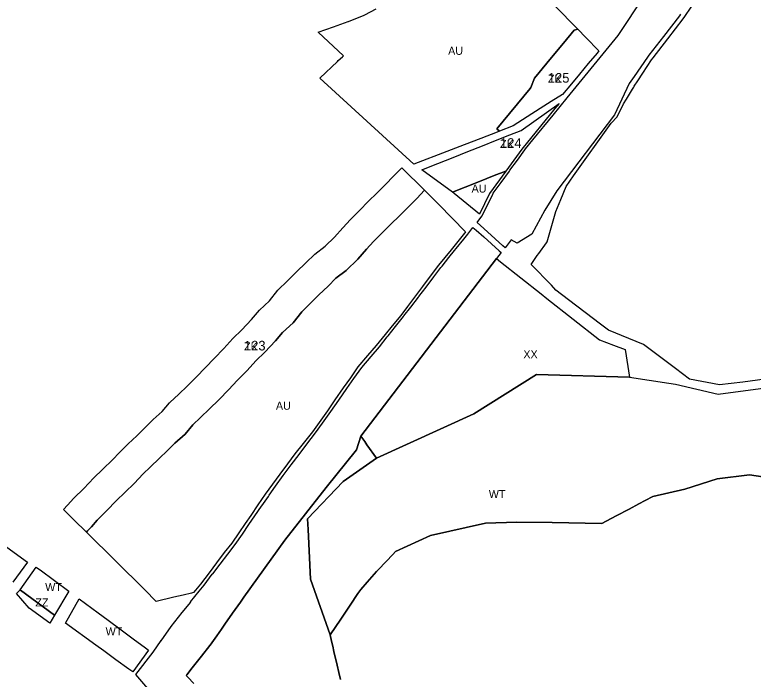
# Model space of a CAD drawing. Extents: x -537068 to -534056, y -1176840 to -1172401.
# Drawn here: x -535533.6 to -535072.7, y -1175950.8 to -1175536.1 of the extents above; entities that cross this region are included whole.
import ezdxf

# ---------------------------------------------------------------- set-up
doc = ezdxf.new("R2010")
doc.units = 0
for name, color, linetype in [('90550013', 7, 'Continuous'), ('90640013', 7, 'Continuous'), ('90670013', 7, 'Continuous'), ('90710023', 7, 'Continuous'), ('90730013', 7, 'Continuous'), ('90750013', 7, 'Continuous'), ('ID_navrh', 7, 'Continuous')]:
    doc.layers.add(name, color=color, linetype=linetype)

msp = doc.modelspace()

# ---------------------------------------------------------------- linework, layer by layer
at = {"layer": '90550013'}
for points in [[(-535050.13, -1175761.47), (-535079.13, -1175765.46), (-535093.81, -1175767.01), (-535112.39, -1175763.44), (-535121.28, -1175756.78), (-535141.07, -1175741.96), (-535150.4, -1175738.16), (-535162.92, -1175733.05), (-535167.89, -1175729.26), (-535192.29, -1175710.66), (-535195.8, -1175707.99), (-535198.63, -1175704.88), (-535211.34, -1175691.91), (-535207.51, -1175686.45), (-535206.57, -1175685.11), (-535201.68, -1175678.47), (-535201.26, -1175677.9), (-535198.75, -1175669.05), (-535195.86, -1175658.84), (-535192.81, -1175651.42), (-535189.46, -1175643.28), (-535184.81, -1175636.58), (-535161.24, -1175603.76), (-535157.66, -1175599.74), (-535153.68, -1175591.72), (-535151.68, -1175588.84), (-535148.03, -1175582.59), (-535147.25, -1175581.25), (-535146.96, -1175580.76), (-535144.78, -1175577.4), (-535141.58, -1175572.48), (-535136.2, -1175564.2), (-535135.2, -1175562.92), (-535125.97, -1175551.1), (-535116.29, -1175538.7), (-535115.3, -1175537.22), (-535107.39, -1175525.43)], [(-535330.29, -1175951), (-535331.33, -1175946.51), (-535332.39, -1175941.92), (-535334.35, -1175933.46), (-535335.09, -1175930.24), (-535335.82, -1175927.11), (-535336.74, -1175923.15), (-535330.15, -1175913.36), (-535324.19, -1175904.5), (-535319.39, -1175897.37), (-535317.62, -1175894.74), (-535313.65, -1175890.19), (-535307.82, -1175883.5), (-535306.83, -1175882.48), (-535301.85, -1175877.35), (-535297.59, -1175872.96), (-535295.86, -1175871.17), (-535274.11, -1175861.12), (-535239.83, -1175853.35), (-535220.25, -1175852.67), (-535198.16, -1175853.04), (-535167.13, -1175853.57), (-535158.18, -1175848.85), (-535150.05, -1175844.57), (-535144.02, -1175841.39), (-535140.05, -1175839.3), (-535135.41, -1175836.85), (-535115.29, -1175832.21), (-535095.1, -1175825.79), (-535075.08, -1175823.28), (-535062.41, -1175825.11)]]:
    msp.add_lwpolyline(points, dxfattribs=at)
msp.add_lwpolyline([(-535307.84, -1175812.81), (-535313.77, -1175804.46), (-535315.14, -1175802.53), (-535317.61, -1175799.04), (-535232.96, -1175688.21), (-535230.41, -1175690.23), (-535204.96, -1175710.36), (-535201.51, -1175713.09), (-535168.68, -1175739.06), (-535159.9, -1175742.34), (-535152.61, -1175745.06), (-535149.83, -1175762.25), (-535207.84, -1175760.65), (-535247.13, -1175785.26)], close=True, dxfattribs=at)
at = {"layer": '90640013'}
for points in [[(-535117.97, -1175535.84), (-535118.65, -1175536.85), (-535128.68, -1175549.71), (-535137.73, -1175561.3), (-535138.67, -1175562.51), (-535146.93, -1175574.59), (-535150.01, -1175579.1), (-535159.16, -1175598.64), (-535195.2, -1175645.89), (-535202.74, -1175658.11), (-535210.95, -1175673.05), (-535220.03, -1175678.6), (-535223.72, -1175676.61), (-535227.6, -1175681.48), (-535228.86, -1175680.34), (-535238.5, -1175671.68), (-535242.98, -1175667.66), (-535245.05, -1175665.69), (-535242.02, -1175661.86), (-535239.38, -1175656.52), (-535235.18, -1175647.99), (-535234.95, -1175647.52), (-535229.99, -1175640.7), (-535224.85, -1175633.62), (-535224.53, -1175633.18), (-535219.88, -1175626.78), (-535215.3, -1175620.47), (-535214.81, -1175619.86), (-535210.21, -1175614.22), (-535197.55, -1175598.71), (-535188.81, -1175587.99), (-535157.02, -1175548.97), (-535140.56, -1175524.19)], [(-535440.26, -1175968.33), (-535457.98, -1175947.84), (-535447.21, -1175933.95), (-535442.17, -1175926.57), (-535442.12, -1175926.9), (-535435.91, -1175917.94), (-535429.03, -1175909.14), (-535423.68, -1175902.65), (-535423.74, -1175902.66), (-535423.87, -1175902.55), (-535418.41, -1175895.85), (-535416.43, -1175893.34), (-535415.4, -1175891.99), (-535410.29, -1175885.31), (-535410.04, -1175884.99), (-535405.39, -1175878.91), (-535400.66, -1175872.73), (-535395.99, -1175866.64), (-535391.55, -1175860.18), (-535387.49, -1175854.29), (-535383.68, -1175848.73), (-535379.57, -1175842.76), (-535379.37, -1175842.48), (-535375.28, -1175836.68), (-535374.77, -1175835.95), (-535370.76, -1175830.27), (-535366.06, -1175823.6), (-535360.98, -1175816.94), (-535356.16, -1175810.6), (-535351.21, -1175804.11), (-535345.85, -1175797.07), (-535341.62, -1175791.07), (-535340.52, -1175789.52), (-535336.42, -1175783.7), (-535331.39, -1175776.57), (-535326.37, -1175769.45), (-535321.9, -1175763.11), (-535317.02, -1175756.28), (-535311.1, -1175749.33), (-535306.01, -1175743.34), (-535301.07, -1175737.11), (-535300.55, -1175736.46), (-535295.93, -1175730.65), (-535291.03, -1175724.47), (-535290.74, -1175724.1), (-535286.29, -1175718.5), (-535281.64, -1175712.35), (-535281.34, -1175711.96), (-535276.9, -1175706.1), (-535272.03, -1175699.66), (-535267.58, -1175693.78), (-535266.92, -1175692.96), (-535262.63, -1175687.65), (-535259.12, -1175683.3), (-535257.99, -1175681.89), (-535253.34, -1175676.14), (-535250.88, -1175673.09), (-535247.58, -1175668.91), (-535245.6, -1175670.57), (-535240.91, -1175674.8), (-535231.26, -1175683.48), (-535230.05, -1175684.56), (-535232.96, -1175688.21), (-535317.61, -1175799.04), (-535320.4, -1175807.66), (-535339.25, -1175831.19), (-535365.13, -1175863.92), (-535390.56, -1175899.49), (-535392.73, -1175902.6), (-535397.63, -1175909.6), (-535402.43, -1175916.46), (-535404.57, -1175919.51), (-535407.43, -1175923.6), (-535410.58, -1175928.09), (-535410.95, -1175928.62), (-535411.89, -1175929.81), (-535417.02, -1175936.3), (-535421.14, -1175941.51), (-535422.81, -1175943.62), (-535426.23, -1175947.95), (-535426.6, -1175948.42), (-535425.64, -1175949.46), (-535421.93, -1175953.47)], [(-535062.41, -1175825.11), (-535075.08, -1175823.28), (-535095.1, -1175825.79), (-535115.29, -1175832.21), (-535135.41, -1175836.85), (-535140.05, -1175839.3), (-535144.02, -1175841.39), (-535150.05, -1175844.57), (-535158.18, -1175848.85), (-535167.13, -1175853.57), (-535198.16, -1175853.04), (-535220.25, -1175852.67), (-535239.83, -1175853.35), (-535274.11, -1175861.12), (-535295.86, -1175871.17), (-535297.59, -1175872.96), (-535301.85, -1175877.35), (-535306.83, -1175882.48), (-535307.82, -1175883.5), (-535313.65, -1175890.19), (-535317.62, -1175894.74), (-535319.39, -1175897.37), (-535324.19, -1175904.5), (-535330.15, -1175913.36), (-535336.74, -1175923.15), (-535349.05, -1175888.24), (-535350.56, -1175857.26), (-535350.95, -1175850.74), (-535328.63, -1175827.45), (-535307.86, -1175812.82), (-535307.84, -1175812.81), (-535247.13, -1175785.26), (-535207.84, -1175760.65), (-535149.83, -1175762.25), (-535125.27, -1175766.1), (-535121.13, -1175766.75), (-535094.47, -1175772.94), (-535024.33, -1175763.57)], [(-535598.9, -1175824.62), (-535525.69, -1175877.72), (-535525.59, -1175877.78), (-535534.77, -1175890.22)]]:
    msp.add_lwpolyline(points, dxfattribs=at)
for points in [[(-535508.75, -1175910.71), (-535530.13, -1175895.14), (-535530.28, -1175894.98), (-535530.28, -1175894.97), (-535520.21, -1175880.83), (-535519.97, -1175880.97), (-535517.79, -1175882.58), (-535499.78, -1175895.9)], [(-535493.32, -1175900.68), (-535481.58, -1175909.37), (-535475.36, -1175913.97), (-535467.29, -1175919.94), (-535459.65, -1175925.59), (-535451.97, -1175931.28), (-535450.09, -1175932.67), (-535459.92, -1175946.27), (-535462.35, -1175944.51), (-535470.45, -1175938.6), (-535477.95, -1175933.14), (-535482.98, -1175929.48), (-535501.85, -1175915.74)]]:
    msp.add_lwpolyline(points, close=True, dxfattribs=at)
at = {"layer": '90670013'}
msp.add_lwpolyline([(-535508.75, -1175910.71), (-535511.8, -1175915.76), (-535524.53, -1175906.37), (-535532.44, -1175897.3), (-535530.28, -1175894.98), (-535530.13, -1175895.14)], close=True, dxfattribs=at)
at = {"layer": '90710023'}
for points in [[(-535182.22, -1175545.09), (-535177.06, -1175550.34), (-535168.98, -1175558.56), (-535170.17, -1175559.99), (-535175.7, -1175566.61), (-535181.13, -1175573.11), (-535186.17, -1175579.15), (-535191.7, -1175585.77), (-535198.7, -1175590.23), (-535205.56, -1175594.61), (-535213.79, -1175599.86), (-535222.6, -1175605.49), (-535230.95, -1175608.71), (-535232.6, -1175607.35), (-535211.88, -1175582.03), (-535211.43, -1175581.48), (-535209.28, -1175575.61), (-535201.52, -1175566.33), (-535196.48, -1175560.29), (-535191.05, -1175553.79), (-535184.33, -1175545.74)], [(-535227.09, -1175633.62), (-535234.36, -1175636.5), (-535243.48, -1175640.11), (-535252.55, -1175643.71), (-535260.36, -1175646.8), (-535279.53, -1175632.88), (-535269.63, -1175628.96), (-535259.91, -1175625.11), (-535250.84, -1175621.52), (-535241.73, -1175617.91), (-535233.53, -1175614.66), (-535224.55, -1175611.11), (-535217.5, -1175608.32), (-535193.82, -1175591.54), (-535196.41, -1175594.7), (-535217.13, -1175620.02)], [(-535503.12, -1175844.96), (-535500.71, -1175842.26), (-535496.67, -1175837.74), (-535490.55, -1175831.73), (-535484.32, -1175825.2), (-535478.81, -1175819.87), (-535478.19, -1175819.27), (-535473.11, -1175814.36), (-535467.8, -1175808.78), (-535462.75, -1175803.92), (-535457.48, -1175798.84), (-535452.46, -1175793.8), (-535447.3, -1175788.74), (-535441.52, -1175783.7), (-535436.99, -1175778.38), (-535436.58, -1175777.9), (-535431.5, -1175773.03), (-535425.89, -1175767.64), (-535420.37, -1175762.32), (-535414.56, -1175756.25), (-535409.2, -1175750.56), (-535403.08, -1175744.29), (-535397.45, -1175738.23), (-535391.82, -1175732.67), (-535385.87, -1175726.27), (-535380.94, -1175720.41), (-535374.5, -1175714.58), (-535369.31, -1175708.05), (-535363.35, -1175702.16), (-535357.8, -1175696.49), (-535351.9, -1175691.02), (-535346.28, -1175685.46), (-535339.91, -1175680.56), (-535334, -1175674.87), (-535328.88, -1175668.99), (-535324.03, -1175663.79), (-535318.28, -1175657.99), (-535312.98, -1175652.65), (-535307.45, -1175647.28), (-535303.45, -1175643.39), (-535302.18, -1175642.08), (-535297.1, -1175636.81), (-535292.07, -1175631.59), (-535277.83, -1175645.64), (-535282.7, -1175650.69), (-535289.28, -1175657.51), (-535293.51, -1175661.62), (-535298.91, -1175666.87), (-535304.08, -1175672.07), (-535309.61, -1175677.65), (-535314.02, -1175682.38), (-535319.49, -1175688.67), (-535326.84, -1175695.74), (-535333.1, -1175700.55), (-535338.06, -1175705.47), (-535343.85, -1175710.83), (-535349.17, -1175716.27), (-535354.4, -1175721.43), (-535359.86, -1175728.31), (-535366.51, -1175734.33), (-535370.88, -1175739.52), (-535377.46, -1175746.6), (-535383.09, -1175752.16), (-535388.6, -1175758.08), (-535394.76, -1175764.4), (-535400.06, -1175770.02), (-535406.2, -1175776.44), (-535412.02, -1175782.05), (-535417.59, -1175787.4), (-535422.37, -1175792.05), (-535427.26, -1175797.8), (-535433.71, -1175803.43), (-535438.37, -1175808), (-535443.45, -1175813.1), (-535448.88, -1175818.32), (-535453.61, -1175822.89), (-535458.91, -1175828.45), (-535464.91, -1175834.25), (-535470.13, -1175839.3), (-535476.3, -1175845.77), (-535482.19, -1175851.55), (-535485.79, -1175855.58), (-535488.2, -1175858.28), (-535488.9, -1175859.05), (-535496.81, -1175851.22)]]:
    msp.add_lwpolyline(points, close=True, dxfattribs=at)
at = {"layer": '90730013'}
msp.add_lwpolyline([(-535421.93, -1175953.47), (-535425.64, -1175949.46), (-535426.6, -1175948.42), (-535426.23, -1175947.95), (-535422.81, -1175943.62), (-535421.14, -1175941.51), (-535417.02, -1175936.3), (-535411.89, -1175929.81), (-535410.95, -1175928.62), (-535410.58, -1175928.09), (-535407.43, -1175923.6), (-535404.57, -1175919.51), (-535402.43, -1175916.46), (-535397.63, -1175909.6), (-535392.73, -1175902.6), (-535390.56, -1175899.49), (-535365.13, -1175863.92), (-535339.25, -1175831.19), (-535320.4, -1175807.66), (-535317.61, -1175799.04), (-535315.14, -1175802.53), (-535313.77, -1175804.46), (-535307.84, -1175812.81), (-535307.86, -1175812.82), (-535328.63, -1175827.45), (-535350.95, -1175850.74), (-535350.56, -1175857.26), (-535349.05, -1175888.24), (-535336.74, -1175923.15), (-535335.82, -1175927.11), (-535335.09, -1175930.24), (-535334.35, -1175933.46), (-535332.39, -1175941.92), (-535331.33, -1175946.51), (-535330.29, -1175951)], dxfattribs=at)
at = {"layer": '90750013'}
msp.add_lwpolyline([(-535196.65, -1175530.43), (-535182.22, -1175545.09), (-535184.33, -1175545.74), (-535191.05, -1175553.79), (-535196.48, -1175560.29), (-535201.52, -1175566.33), (-535209.28, -1175575.61), (-535211.43, -1175581.48), (-535211.88, -1175582.03), (-535232.6, -1175607.35), (-535230.95, -1175608.71), (-535232.44, -1175609.28), (-535242.74, -1175613.24), (-535253.07, -1175617.21), (-535263.82, -1175621.35), (-535284.44, -1175629.29), (-535343.16, -1175575.62), (-535332.12, -1175565.19), (-535331.65, -1175564.74), (-535329.07, -1175562.3), (-535328.41, -1175561.68), (-535344.32, -1175546.98), (-535334.71, -1175543.59), (-535325.49, -1175540.34), (-535325.24, -1175540.24), (-535315.59, -1175536.42), (-535315.16, -1175536.2), (-535307.97, -1175532.5)], dxfattribs=at)
for points in [[(-535227.09, -1175633.62), (-535237.35, -1175647.63), (-535243.62, -1175660.53), (-535259.3, -1175647.57), (-535260.36, -1175646.8), (-535252.55, -1175643.71), (-535243.48, -1175640.11), (-535234.36, -1175636.5)], [(-535488.9, -1175859.05), (-535488.2, -1175858.28), (-535485.79, -1175855.58), (-535482.19, -1175851.55), (-535476.3, -1175845.77), (-535470.13, -1175839.3), (-535464.91, -1175834.25), (-535458.91, -1175828.45), (-535453.61, -1175822.89), (-535448.88, -1175818.32), (-535443.45, -1175813.1), (-535438.37, -1175808), (-535433.71, -1175803.43), (-535427.26, -1175797.8), (-535422.37, -1175792.05), (-535417.59, -1175787.4), (-535412.02, -1175782.05), (-535406.2, -1175776.44), (-535400.06, -1175770.02), (-535394.76, -1175764.4), (-535388.6, -1175758.08), (-535383.09, -1175752.16), (-535377.46, -1175746.6), (-535370.88, -1175739.52), (-535366.51, -1175734.33), (-535359.86, -1175728.31), (-535354.4, -1175721.43), (-535349.17, -1175716.27), (-535343.85, -1175710.83), (-535338.06, -1175705.47), (-535333.1, -1175700.55), (-535326.84, -1175695.74), (-535319.49, -1175688.67), (-535314.02, -1175682.38), (-535309.61, -1175677.65), (-535304.08, -1175672.07), (-535298.91, -1175666.87), (-535293.51, -1175661.62), (-535289.28, -1175657.51), (-535282.7, -1175650.69), (-535277.83, -1175645.64), (-535268.8, -1175654.55), (-535252.29, -1175671.63), (-535252.69, -1175672.14), (-535252.87, -1175672.38), (-535261.11, -1175682.71), (-535269.07, -1175692.43), (-535274.35, -1175699.26), (-535279.07, -1175705.67), (-535283.55, -1175711.47), (-535288.41, -1175718.1), (-535292.71, -1175723.69), (-535298.03, -1175730.3), (-535302.47, -1175735.7), (-535307.98, -1175742.53), (-535313.4, -1175748.77), (-535319.4, -1175755.73), (-535324.06, -1175762.7), (-535328.58, -1175768.96), (-535333.76, -1175776.49), (-535338.4, -1175783.34), (-535342.64, -1175789.05), (-535347.76, -1175796.36), (-535353.58, -1175803.58), (-535358.7, -1175810.03), (-535363.4, -1175816.29), (-535368.22, -1175822.74), (-535377.28, -1175835.27), (-535381.9, -1175841.97), (-535386.27, -1175848.61), (-535389.71, -1175853.51), (-535393.74, -1175859.47), (-535398.2, -1175865.9), (-535402.84, -1175871.73), (-535407.69, -1175878.19), (-535412.35, -1175884.45), (-535417.77, -1175891.54), (-535420.76, -1175895.17), (-535422.03, -1175896.71), (-535423.33, -1175897.02), (-535428.55, -1175898.25), (-535434.4, -1175899.64), (-535445.31, -1175902.23), (-535452.5, -1175895.1)]]:
    msp.add_lwpolyline(points, close=True, dxfattribs=at)

# ---------------------------------------------------------------- texts
at = {"layer": '90550013'}
msp.add_text('XX', height=5, rotation=0, dxfattribs=at).set_placement((-535216.14, -1175750.51))
at = {"layer": '90640013'}
for p in [(-535237.71, -1175837.68), (-535514.61, -1175895.77), (-535476.87, -1175923.48)]:
    msp.add_text('WT', height=5, rotation=0, dxfattribs=at).set_placement(p)
at = {"layer": '90670013'}
msp.add_text('ZZ', height=5, rotation=360, dxfattribs=at).set_placement((-535520.74, -1175905.37))
at = {"layer": '90710023'}
for rotation, p in [(0, (-535200.79, -1175578.51)), (360, (-535230.67, -1175619.17)), (360, (-535390.47, -1175745.61))]:
    msp.add_text('ZK', height=5, rotation=rotation, dxfattribs=at).set_placement(p)
at = {"layer": '90750013'}
for rotation, p in [(360, (-535263.1, -1175561.1)), (360, (-535248.46, -1175647.07)), (0, (-535370.59, -1175782.6))]:
    msp.add_text('AU', height=5, rotation=rotation, dxfattribs=at).set_placement(p)
at = {"layer": 'ID_navrh'}
for s, rotation, p in [('125', 0, (-535200.79, -1175578.51)), ('124', 0, (-535230.67, -1175619.17)), ('123', 360, (-535390.47, -1175745.61))]:
    msp.add_text(s, height=6, rotation=rotation, dxfattribs=at).set_placement(p)

doc.saveas('drawing.dxf')
